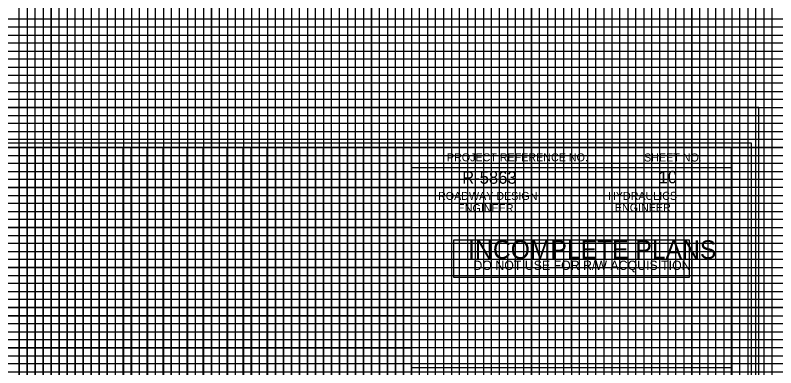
# Model space of a CAD drawing. Extents: x 553912 to 567693, y 512355 to 537539.
# Drawn here: x 566753.9 to 567228.9, y 514327.2 to 514547.2 of the extents above; entities that cross this region are included whole.
import ezdxf

# ---------------------------------------------------------------- set-up
doc = ezdxf.new("R2010")
doc.units = 0
for name, color, linetype in [('Old_Level_42', 7, 'Continuous'), ('Old_Level_54', 7, 'Continuous'), ('Prop ROW Permanent Easement CELL', 7, 'Continuous'), ('Sheet Cutting Line CELL', 7, 'Continuous'), ('Sheet Data Field CELL', 7, 'Continuous'), ('Sheet DOT Grid CELL', 7, 'Continuous'), ('Sheet Plot Border Inside CELL', 7, 'Continuous'), ('Sheet Plot Border Outside CELL', 7, 'Continuous'), ('Sheet Profile CELL', 7, 'Continuous'), ('Sheet Profile Grid Major CELL', 7, 'Continuous'), ('Sheet Profile Grid Middle CELL', 7, 'Continuous'), ('Sheet Profile Grid Minor CELL', 7, 'Continuous'), ('Sheet Sticker Incomplete CELL', 7, 'Continuous'), ('Sheet Summary Guardrail CELL', 7, 'Continuous')]:
    doc.layers.add(name, color=color, linetype=linetype)

msp = doc.modelspace()

# ---------------------------------------------------------------- linework, layer by layer
at = {"layer": 'Old_Level_42'}
for p, q in [((566776.42, 514839.71), (566776.42, 513814.71)), ((566826.42, 514839.71), (566826.42, 513814.71)), ((566876.42, 514839.71), (566876.42, 513814.71)), ((566926.42, 514839.71), (566926.42, 513814.71)), ((566976.42, 514839.71), (566976.42, 513814.71)), ((567026.42, 514839.71), (567026.42, 513814.71)), ((567076.42, 514839.71), (567076.42, 513814.71)), ((567126.42, 514839.71), (567126.42, 513814.71)), ((567176.42, 514839.71), (567176.42, 513814.71)), ((567226.42, 514839.71), (567226.42, 513814.71)), ((566176.42, 514514.71), (567676.42, 514514.71)), ((566176.42, 514464.71), (567676.42, 514464.71)), ((566176.42, 514414.71), (567676.42, 514414.71)), ((566176.42, 514364.71), (567676.42, 514364.71))]:
    msp.add_line(p, q, dxfattribs=at)
at = {"layer": 'Old_Level_54'}
for points in [[(566776.42, 513814.71), (566776.42, 514839.71), (566826.42, 514839.71), (566826.42, 513814.71)], [(566876.42, 513814.71), (566876.42, 514839.71), (566926.42, 514839.71), (566926.42, 513814.71)], [(566976.42, 513814.71), (566976.42, 514839.71), (567026.42, 514839.71), (567026.42, 513814.71)], [(567076.42, 513814.71), (567076.42, 514839.71), (567126.42, 514839.71), (567126.42, 513814.71)], [(567176.42, 513814.71), (567176.42, 514839.71), (567226.42, 514839.71), (567226.42, 513814.71)], [(567676.42, 514464.71), (566176.42, 514464.71), (566176.42, 514514.71), (567676.42, 514514.71)], [(567676.42, 514364.71), (566176.42, 514364.71), (566176.42, 514414.71), (567676.42, 514414.71)]]:
    msp.add_lwpolyline(points, dxfattribs=at)
at = {"layer": 'Prop ROW Permanent Easement CELL'}
for points in [[(566751.42, 514839.71), (566801.42, 514839.71), (566801.42, 513814.71)], [(566851.42, 513814.71), (566851.42, 514839.71), (566901.42, 514839.71), (566901.42, 513814.71)], [(566951.42, 513814.71), (566951.42, 514839.71), (567001.42, 514839.71), (567001.42, 513814.71)], [(567051.42, 513814.71), (567051.42, 514839.71), (567101.42, 514839.71), (567101.42, 513814.71)], [(567151.42, 513814.71), (567151.42, 514839.71), (567201.42, 514839.71), (567201.42, 513814.71)], [(567676.42, 514539.71), (566176.42, 514539.71), (566176.42, 514489.71), (567676.42, 514489.71)], [(567676.42, 514439.71), (566176.42, 514439.71), (566176.42, 514389.71), (567676.42, 514389.71)], [(567676.42, 514339.71), (566176.42, 514339.71), (566176.42, 514289.71), (567676.42, 514289.71)]]:
    msp.add_lwpolyline(points, dxfattribs=at)
at = {"layer": 'Sheet Cutting Line CELL'}
msp.add_line((567218.35, 514489.72), (565534.35, 514489.72), dxfattribs=at)
at = {"layer": 'Sheet DOT Grid CELL'}
for p, q in [((566801.35, 513964.72), (566801.35, 514464.72)), ((566851.35, 513964.72), (566851.35, 514464.72)), ((566901.35, 513964.72), (566901.35, 514464.72)), ((566951.35, 513964.72), (566951.35, 514464.72)), ((567001.3, 514414.72), (565701.35, 514414.72)), ((567001.3, 514364.72), (565701.35, 514364.72))]:
    msp.add_line(p, q, dxfattribs=at)
at = {"layer": 'Sheet Plot Border Inside CELL'}
msp.add_lwpolyline([(565547.35, 513412.17), (567213.85, 513412.17), (567213.85, 514467.27), (565547.35, 514467.27)], close=True, dxfattribs=at)
at = {"layer": 'Sheet Plot Border Outside CELL'}
msp.add_lwpolyline([(565534.35, 513389.72), (567218.35, 513389.72), (567218.35, 514489.72), (565534.35, 514489.72)], close=True, dxfattribs=at)
at = {"layer": 'Sheet Profile CELL'}
for p, q in [((567126.35, 514464.67), (567126.35, 514439.67)), ((567001.3, 514452.17), (567201.35, 514452.17)), ((567101.35, 514439.67), (567101.35, 514327.22))]:
    msp.add_line(p, q, dxfattribs=at)
for points in [[(567201.35, 514464.72), (565701.35, 514464.72), (565701.35, 513414.72), (567201.35, 513414.72)], [(567001.3, 514464.72), (567201.35, 514464.72), (567201.35, 514439.67), (567001.3, 514439.67)], [(567001.3, 514439.67), (567101.35, 514439.67), (567101.35, 514327.17), (567001.3, 514327.17)], [(567101.35, 514439.67), (567201.35, 514439.67), (567201.35, 514327.17), (567101.35, 514327.17)]]:
    msp.add_lwpolyline(points, close=True, dxfattribs=at)
at = {"layer": 'Sheet Profile Grid Major CELL'}
for points in [[(566751.35, 513964.72), (566801.35, 513964.72), (566801.35, 514464.72), (566851.35, 514464.72), (566851.35, 513964.72), (566901.35, 513964.72), (566901.35, 514464.72), (566951.35, 514464.72), (566951.35, 513964.72), (567001.35, 513964.72), (567001.35, 514464.72), (567027.65, 514464.72)], [(565701.35, 514414.72), (567001.35, 514414.72)], [(567001.35, 514364.72), (565701.35, 514364.72), (565701.35, 514314.72), (567001.35, 514314.72)]]:
    msp.add_lwpolyline(points, dxfattribs=at)
at = {"layer": 'Sheet Profile Grid Middle CELL'}
msp.add_line((565701.35, 514439.72), (567001.3, 514439.72), dxfattribs=at)
for points in [[(566726.35, 514464.72), (566776.35, 514464.72), (566776.35, 513964.72), (566826.35, 513964.72), (566826.35, 514464.72), (566876.35, 514464.72), (566876.35, 513964.72), (566926.35, 513964.72), (566926.35, 514464.72), (566976.35, 514464.72), (566976.35, 513964.72), (567026.35, 513964.72), (567026.35, 514303.67)], [(567001.35, 514389.72), (565701.35, 514389.72), (565701.35, 514339.72), (567001.35, 514339.72)]]:
    msp.add_lwpolyline(points, dxfattribs=at)
at = {"layer": 'Sheet Profile Grid Minor CELL'}
for p, q in [((565751.35, 514459.72), (567001.35, 514459.72)), ((567001.35, 514454.72), (565751.35, 514454.37)), ((565751.35, 514449.72), (567001.35, 514449.72)), ((567001.3, 514329.72), (565751.35, 514329.72))]:
    msp.add_line(p, q, dxfattribs=at)
for points in [[(566746.35, 514464.72), (566756.35, 514464.72), (566756.35, 513964.72)], [(566761.35, 513964.72), (566761.35, 514464.72), (566766.35, 514464.72), (566766.35, 513964.72)], [(566771.35, 513964.72), (566771.35, 514464.72), (566781.35, 514464.72), (566781.35, 513964.72)], [(566786.35, 513964.72), (566786.35, 514464.72), (566791.35, 514464.72), (566791.35, 513964.72)], [(566796.35, 513964.72), (566796.35, 514464.72), (566806.35, 514464.72), (566806.35, 513964.72)], [(566811.35, 513964.72), (566811.35, 514464.72), (566816.35, 514464.72), (566816.35, 513964.72)], [(566821.35, 513964.72), (566821.35, 514464.72), (566831.35, 514464.72), (566831.35, 513964.72)], [(566836.35, 513964.72), (566836.35, 514464.72), (566841.35, 514464.72), (566841.35, 513964.72)], [(566846.35, 513964.72), (566846.35, 514464.72), (566856.35, 514464.72), (566856.35, 513964.72)], [(566861.35, 513964.72), (566861.35, 514464.72), (566866.35, 514464.72), (566866.35, 513964.72)], [(566871.35, 513964.72), (566871.35, 514464.72), (566881.35, 514464.72), (566881.35, 513964.72)], [(566886.35, 513964.72), (566886.35, 514464.72), (566891.35, 514464.72), (566891.35, 513964.72)], [(566896.35, 513964.72), (566896.35, 514464.72), (566906.35, 514464.72), (566906.35, 513964.72)], [(566911.35, 513964.72), (566911.35, 514464.72), (566916.35, 514464.72), (566916.35, 513964.72)], [(566921.35, 513964.72), (566921.35, 514464.72), (566931.35, 514464.72), (566931.35, 513964.72)], [(566936.35, 513964.72), (566936.35, 514464.72), (566941.35, 514464.72), (566941.35, 513964.72)], [(566946.35, 513964.72), (566946.35, 514464.72), (566956.35, 514464.72), (566956.35, 513964.72)], [(566961.35, 513964.72), (566961.35, 514464.72), (566966.35, 514464.72), (566966.35, 513964.72)], [(566971.35, 513964.72), (566971.35, 514464.72), (566981.35, 514464.72), (566981.35, 513964.72)], [(566986.35, 513964.72), (566986.35, 514464.72), (566991.35, 514464.72), (566991.35, 513964.72)], [(566996.35, 513964.72), (566996.35, 514464.72), (567006.35, 514464.72)], [(567001.35, 514444.72), (565751.35, 514444.72), (565751.35, 514434.72), (567001.35, 514434.72)], [(567001.3, 514429.72), (565751.35, 514429.72), (565751.35, 514424.72), (567001.35, 514424.72)], [(567001.35, 514419.72), (565751.35, 514419.72), (565751.35, 514409.72), (567001.35, 514409.72)], [(567001.35, 514404.72), (565751.35, 514404.72), (565751.35, 514399.72), (567001.35, 514399.72)], [(567001.35, 514394.72), (565751.35, 514394.72), (565751.35, 514384.72), (567001.35, 514384.72)], [(567001.35, 514379.72), (565751.35, 514379.72), (565751.35, 514374.72), (567001.35, 514374.72)], [(567001.35, 514369.72), (565751.35, 514369.72), (565751.35, 514359.72), (567001.35, 514359.72)], [(567001.35, 514354.62), (565751.45, 514354.62), (565751.45, 514349.72), (567001.35, 514349.72)], [(567001.35, 514344.72), (565751.35, 514344.72), (565751.35, 514334.72), (567001.35, 514334.72)]]:
    msp.add_lwpolyline(points, dxfattribs=at)
at = {"layer": 'Sheet Sticker Incomplete CELL'}
msp.add_lwpolyline([(567027.87, 514383.51), (567027.87, 514407.01), (567174.87, 514407.01), (567174.87, 514383.51)], close=True, dxfattribs=at)
at = {"layer": 'Sheet Summary Guardrail CELL'}
for points in [[(566756.42, 513814.71), (566756.42, 514839.71), (566761.42, 514839.71), (566761.42, 513814.71)], [(566766.42, 513814.71), (566766.42, 514839.71), (566771.42, 514839.71), (566771.42, 513814.71)], [(566781.42, 513814.71), (566781.42, 514839.71), (566786.42, 514839.71), (566786.42, 513814.71)], [(566791.42, 513814.71), (566791.42, 514839.71), (566796.42, 514839.71), (566796.42, 513814.71)], [(566806.42, 513814.71), (566806.42, 514839.71), (566811.42, 514839.71), (566811.42, 513814.71)], [(566816.42, 513814.71), (566816.42, 514839.71), (566821.42, 514839.71), (566821.42, 513814.71)], [(566831.42, 513814.71), (566831.42, 514839.71), (566836.42, 514839.71), (566836.42, 513814.71)], [(566841.42, 513814.71), (566841.42, 514839.71), (566846.42, 514839.71), (566846.42, 513814.71)], [(566856.42, 513814.71), (566856.42, 514839.71), (566861.42, 514839.71), (566861.42, 513814.71)], [(566866.42, 513814.71), (566866.42, 514839.71), (566871.42, 514839.71), (566871.42, 513814.71)], [(566881.42, 513814.71), (566881.42, 514839.71), (566886.42, 514839.71), (566886.42, 513814.71)], [(566891.42, 513814.71), (566891.42, 514839.71), (566896.42, 514839.71), (566896.42, 513814.71)], [(566906.42, 513814.71), (566906.42, 514839.71), (566911.42, 514839.71), (566911.42, 513814.71)], [(566916.42, 513814.71), (566916.42, 514839.71), (566921.42, 514839.71), (566921.42, 513814.71)], [(566931.42, 513814.71), (566931.42, 514839.71), (566936.42, 514839.71), (566936.42, 513814.71)], [(566941.42, 513814.71), (566941.42, 514839.11), (566946.42, 514839.11), (566946.42, 513814.71)], [(566956.42, 513814.71), (566956.42, 514839.71), (566961.42, 514839.71), (566961.42, 513814.71)], [(566966.42, 513814.71), (566966.42, 514839.71), (566971.42, 514839.71), (566971.42, 513814.71)], [(566981.42, 513814.71), (566981.42, 514839.71), (566986.42, 514839.71), (566986.42, 513814.71)], [(566991.42, 513814.71), (566991.42, 514839.71), (566996.42, 514839.71), (566996.42, 513814.71)], [(567006.42, 513814.71), (567006.42, 514839.71), (567011.42, 514839.71), (567011.42, 513814.71)], [(567016.42, 513814.71), (567016.42, 514839.71), (567021.42, 514839.71), (567021.42, 513814.71)], [(567031.42, 513814.71), (567031.42, 514839.71), (567036.42, 514839.71), (567036.42, 513814.71)], [(567041.42, 513814.71), (567041.42, 514839.71), (567046.42, 514839.71), (567046.42, 513814.71)], [(567056.42, 513814.71), (567056.42, 514839.71), (567061.42, 514839.71), (567061.42, 513814.71)], [(567066.42, 513814.71), (567066.42, 514839.71), (567071.42, 514839.71), (567071.42, 513814.71)], [(567081.42, 513814.71), (567081.42, 514839.71), (567086.42, 514839.71), (567086.42, 513814.71)], [(567091.42, 513814.71), (567091.42, 514839.71), (567096.42, 514839.71), (567096.42, 513814.71)], [(567106.42, 513814.71), (567106.42, 514839.71), (567111.42, 514839.71), (567111.42, 513814.71)], [(567116.42, 513814.71), (567116.42, 514839.71), (567121.42, 514839.71), (567121.42, 513814.71)], [(567131.42, 513814.71), (567131.42, 514839.71), (567136.42, 514839.71), (567136.42, 513814.71)], [(567141.42, 513814.71), (567141.42, 514839.71), (567146.42, 514839.71), (567146.42, 513814.71)], [(567156.42, 513814.71), (567156.42, 514839.71), (567161.42, 514839.71), (567161.42, 513814.71)], [(567166.42, 513814.71), (567166.42, 514839.71), (567171.42, 514839.71), (567171.42, 513814.71)], [(567181.42, 513814.71), (567181.42, 514839.71), (567186.42, 514839.71), (567186.42, 513814.71)], [(567191.42, 513814.71), (567191.42, 514839.71), (567196.42, 514839.71), (567196.42, 513814.71)], [(567206.42, 513814.71), (567206.42, 514839.71), (567211.42, 514839.71), (567211.42, 513814.71)], [(567216.42, 513814.71), (567216.42, 514839.71), (567221.42, 514839.71), (567221.42, 513814.71)], [(567626.42, 514544.71), (566226.42, 514544.71), (566226.42, 514534.71), (567626.42, 514534.71)], [(567626.42, 514529.71), (566226.42, 514529.71), (566226.42, 514524.71), (567626.42, 514524.71)], [(567626.42, 514519.71), (566226.42, 514519.71), (566226.42, 514509.71), (567626.42, 514509.71)], [(567626.42, 514504.71), (566226.42, 514504.71), (566226.42, 514499.71), (567626.42, 514499.71)], [(567626.42, 514494.71), (566226.42, 514494.71), (566226.42, 514484.71), (567626.42, 514484.71)], [(567626.42, 514479.71), (566226.42, 514479.71), (566226.42, 514474.71), (567626.42, 514474.71)], [(567626.42, 514469.71), (566226.42, 514469.71), (566226.42, 514459.71), (567626.42, 514459.71)], [(567626.42, 514454.71), (566226.42, 514454.71), (566226.42, 514449.71), (567626.42, 514449.71)], [(567626.42, 514444.71), (566226.42, 514444.71), (566226.42, 514434.71), (567626.42, 514434.71)], [(567626.42, 514429.71), (566226.42, 514429.71), (566226.42, 514424.71), (567626.42, 514424.71)], [(567626.42, 514419.71), (566226.42, 514419.71), (566226.42, 514409.71), (567626.42, 514409.71)], [(567626.42, 514404.71), (566226.42, 514404.71), (566226.42, 514399.71), (567626.42, 514399.71)], [(567626.42, 514394.71), (566226.42, 514394.71), (566226.42, 514384.71), (567626.42, 514384.71)], [(567626.42, 514379.71), (566226.42, 514379.71), (566226.42, 514374.71), (567626.42, 514374.71)], [(567626.42, 514369.71), (566226.42, 514369.71), (566226.42, 514359.71), (567626.42, 514359.71)], [(567626.42, 514354.71), (566226.42, 514354.71), (566226.42, 514349.71), (567626.42, 514349.71)], [(567626.42, 514344.71), (566226.42, 514344.71), (566226.42, 514334.71), (567626.42, 514334.71)], [(567626.42, 514329.71), (566226.42, 514329.71), (566226.42, 514324.71), (567626.42, 514324.71)]]:
    msp.add_lwpolyline(points, dxfattribs=at)

# ---------------------------------------------------------------- texts
at = {"layer": 'Sheet Data Field CELL'}
for s, p in [('R-5863   ', (567033.08, 514442.03)), ('10 ', (567155.74, 514442.33))]:
    msp.add_text(s, height=7.75, dxfattribs=at).set_placement(p)
at = {"layer": 'Sheet Profile CELL'}
for s, height, p in [('PROJECT REFERENCE NO.', 5.0001, (567023.52, 514456.03)), ('SHEET NO.', 5, (567146.67, 514455.93)), ('ROADWAY DESIGN', 5.0001, (567017.97, 514431.93)), ('HYDRAULICS', 5, (567124.17, 514431.98)), ('ENGINEER', 5, (567128.42, 514424.63)), ('ENGINEER', 5, (567030.22, 514424.33))]:
    msp.add_text(s, height=height, dxfattribs=at).set_placement(p)
at = {"layer": 'Sheet Sticker Incomplete CELL'}
for s, height, p in [('INCOMPLETE PLANS', 11.52, (567036.82, 514395.21)), ('DO NOT USE FOR R/W ACQUISITION', 5.76, (567040.07, 514388.26))]:
    msp.add_text(s, height=height, dxfattribs=at).set_placement(p)

doc.saveas('drawing.dxf')
